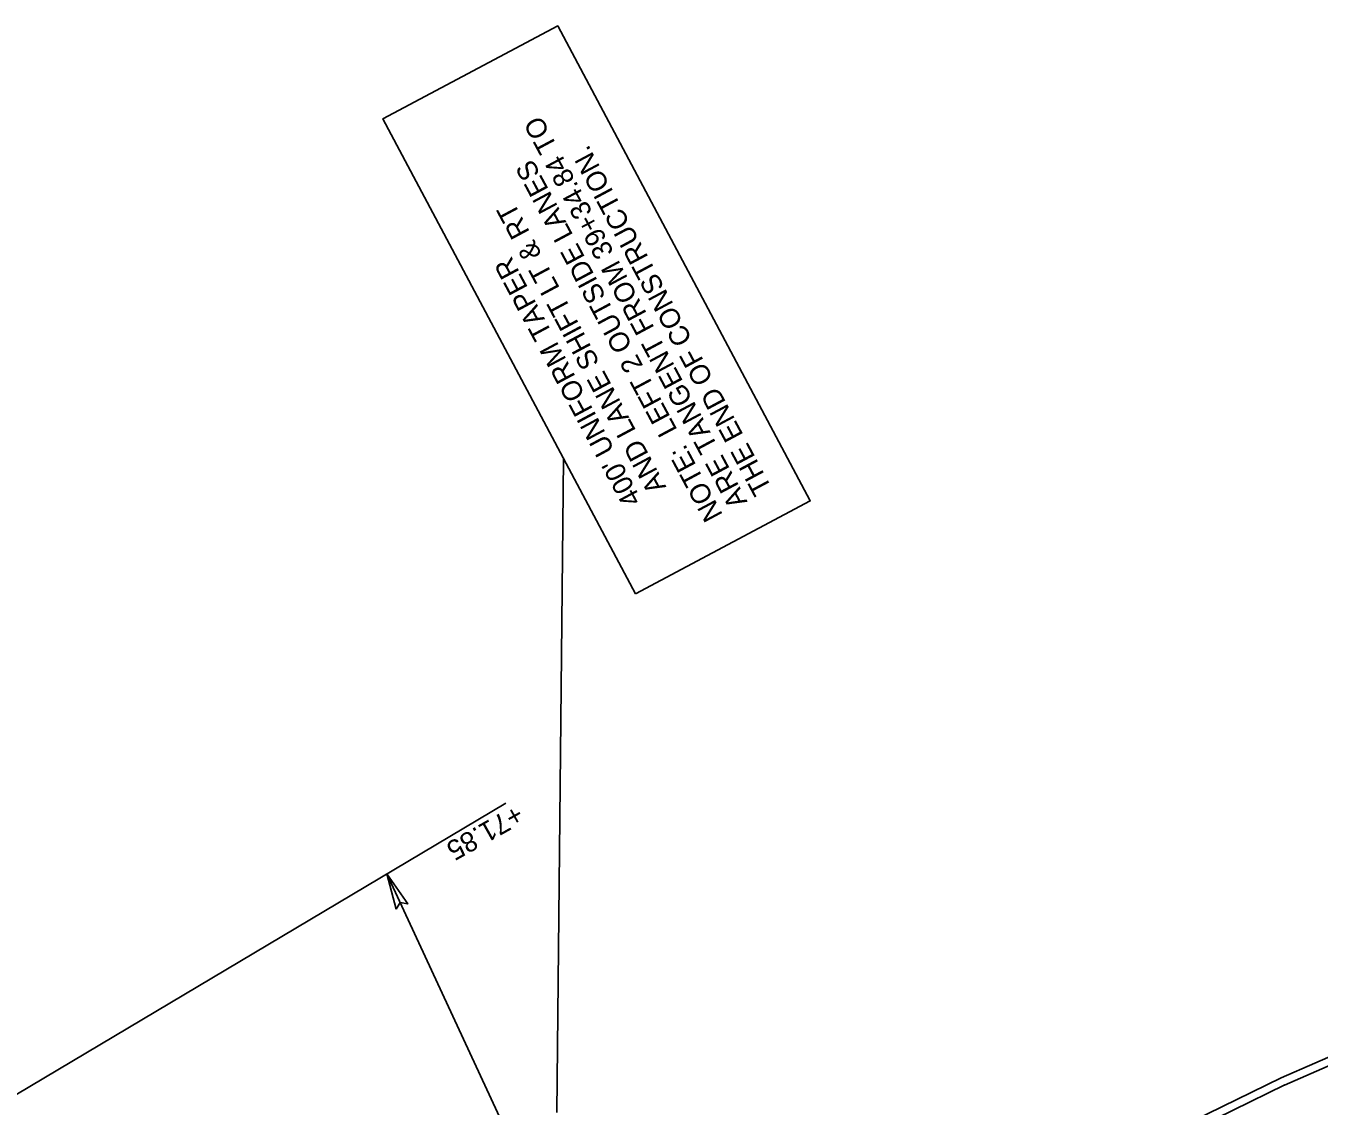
# Model space of a CAD drawing. Extents: x 2389099 to 2405615, y 552200 to 573532.
# Drawn here: x 2402460.2 to 2402784.3, y 571201 to 571471.8 of the extents above; entities that cross this region are included whole.
import ezdxf

# ---------------------------------------------------------------- set-up
doc = ezdxf.new("R2010")
doc.units = 0
for name, color, linetype in [('Old_Level_11', 7, 'Continuous'), ('Prop Conc Expressway Gutter', 7, 'Continuous'), ('Prop Dimension', 7, 'Continuous'), ('Prop Dimension Text', 7, 'Continuous'), ('Prop EOT', 7, 'Continuous'), ('Prop Guardrail', 7, 'Continuous'), ('Prop Horizontal Alignment', 7, 'Continuous')]:
    doc.layers.add(name, color=color, linetype=linetype)

msp = doc.modelspace()

# ---------------------------------------------------------------- linework, layer by layer
at = {"layer": 'Prop Conc Expressway Gutter'}
for p, q in [((2403050.91, 571326.93), (2402775.66, 571206.31)), ((2402682.87, 571161.14), (2402775.73, 571206.34))]:
    msp.add_line(p, q, dxfattribs=at)
at = {"layer": 'Prop Dimension'}
for p, q in [((2402594.95, 571363.33), (2402593.25, 571199.44)), ((2402580.47, 571277.03), (2402454.13, 571201.76)), ((2402550.65, 571259.26), (2402728.17, 570876.89))]:
    msp.add_line(p, q, dxfattribs=at)
for points in [[(2402612.96, 571329.44), (2402549.64, 571448.53), (2402593.49, 571471.85), (2402656.81, 571352.76)], [(2402553.03, 571250.45), (2402550.65, 571259.26), (2402555.91, 571251.73), (2402553.97, 571252.1)]]:
    msp.add_lwpolyline(points, close=True, dxfattribs=at)
at = {"layer": 'Prop EOT'}
for p in [(2403050.11, 571328.76), (2402681.99, 571162.94)]:
    msp.add_line(p, (2402774.86, 571208.14), dxfattribs=at)
at = {"layer": 'Prop Guardrail'}
for p, q in [((2402937.62, 571279.56), (2402774.86, 571208.14)), ((2402774.86, 571208.14), (2402743.33, 571192.8))]:
    msp.add_line(p, q, dxfattribs=at)
at = {"layer": 'Prop Horizontal Alignment'}
msp.add_arc((2399929.8, 569697.99), 2887.13, 22.84477, 37.67936, dxfattribs=at)

# ---------------------------------------------------------------- texts
at = {"layer": 'Old_Level_11'}
for s, p in [('AND LANE SHIFT LT & RT', (2402620.77, 571356.25)), ("400' UNIFORM TAPER", (2402614.6, 571352.95))]:
    msp.add_text(s, height=5, rotation=118.1463, dxfattribs=at).set_placement(p)
at = {"layer": 'Prop Dimension Text'}
for s, rotation, p in [('ARE TANGENT FROM 39+34.84 TO ', 118.1463, (2402641.14, 571352.54)), ('THE END OF CONSTRUCTION.', 118.1463, (2402647.32, 571355.84)), ('NOTE:  LEFT 2 OUTSIDE LANES', 118.1463, (2402634.97, 571349.24)), ('+71.85', 209.3599, (2402583.13, 571276.84))]:
    msp.add_text(s, height=5, rotation=rotation, dxfattribs=at).set_placement(p)

doc.saveas('drawing.dxf')
